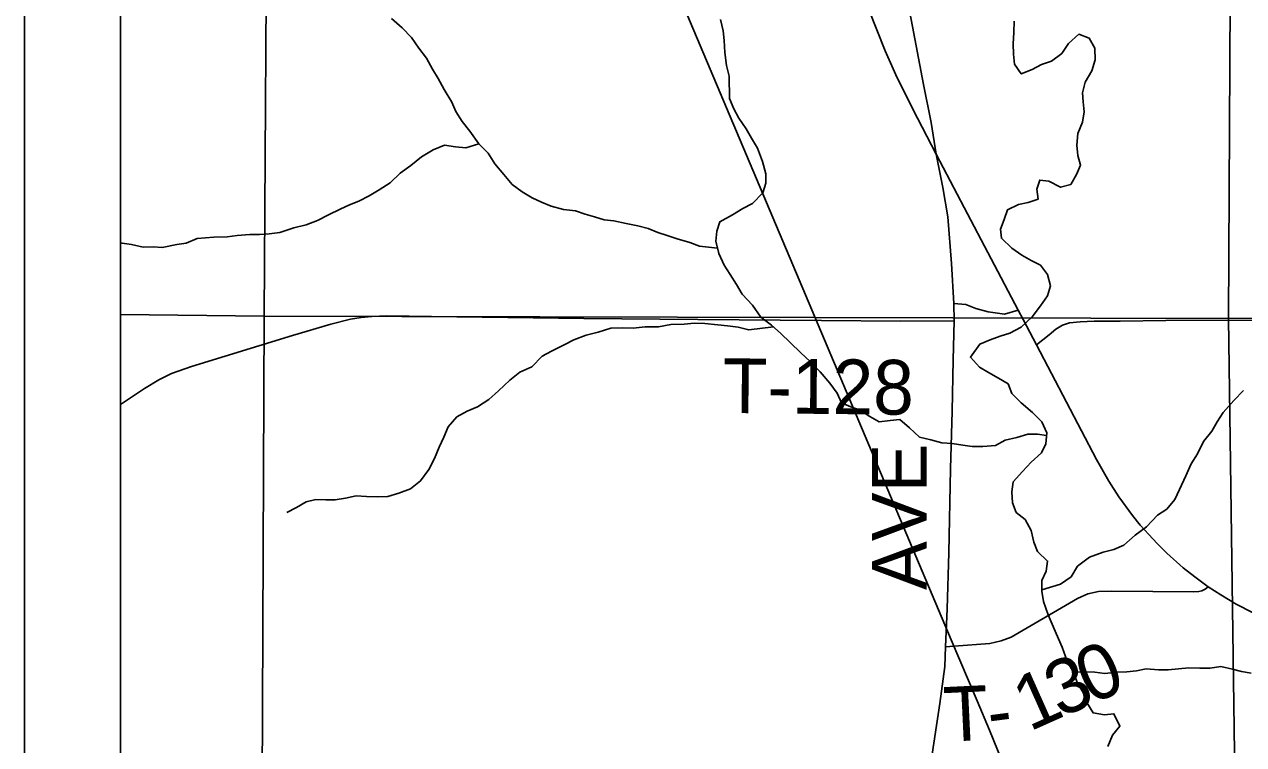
# Model space of a CAD drawing. Extents: x 0 to 34, y 0 to 22.
# Drawn here: x 2 to 3.267, y 17.55 to 18.298 of the extents above; entities that cross this region are included whole.
import ezdxf

# ---------------------------------------------------------------- set-up
doc = ezdxf.new("R2010")
doc.units = 0
for name, color, linetype in [('Default', 7, 'Continuous'), ('SH_Cut_Line', 7, 'Continuous'), ('SH_Data', 7, 'Continuous')]:
    doc.layers.add(name, color=color, linetype=linetype)

msp = doc.modelspace()

# ---------------------------------------------------------------- linework, layer by layer
at = {"layer": 'Default'}
for p, q in [((2.9665, 17.9898), (2.9659, 18.0078)), ((2.9659, 18.0078), (2.9665, 17.9898))]:
    msp.add_line(p, q, dxfattribs=at)
for points in [[(2.1, 20.9), (2.1, 17.0156)], [(2.9478, 18.1631), (2.9423, 18.1959), (2.9345, 18.2352), (2.909, 18.3706), (2.8997, 18.4145)], [(3.0159, 17.5333), (3.0031, 17.5646), (2.9901, 17.5953), (2.9633, 17.6587), (2.9067, 17.7923), (2.7985, 18.0482), (2.6541, 18.39)], [(2.8772, 18.3138), (2.8945, 18.2702), (2.9057, 18.2453), (2.9161, 18.2244), (2.9284, 18.2002), (2.9478, 18.1631)], [(2.7204, 18.0653), (2.7018, 18.0675), (2.6915, 18.0712), (2.6786, 18.0749), (2.668, 18.0785), (2.6585, 18.0815), (2.6482, 18.0859), (2.6376, 18.0885), (2.6254, 18.091), (2.6125, 18.0939), (2.6027, 18.0949), (2.5924, 18.0979), (2.5829, 18.1008), (2.5727, 18.1041), (2.5602, 18.1055), (2.5476, 18.1088), (2.5374, 18.1132), (2.5278, 18.1177), (2.5172, 18.124), (2.5069, 18.1315), (2.4984, 18.142), (2.4888, 18.153), (2.4819, 18.1639), (2.4723, 18.1736), (2.463, 18.1868), (2.455, 18.197), (2.4484, 18.2072), (2.4441, 18.217), (2.4364, 18.2302), (2.4302, 18.2415), (2.424, 18.2513), (2.4178, 18.2626), (2.4101, 18.2732), (2.4024, 18.2841), (2.3925, 18.2942), (2.3817, 18.304)], [(3.0624, 17.8709), (3.0528, 17.8723), (3.043, 17.8722), (3.0313, 17.8687), (3.0192, 17.8659), (3.0094, 17.8605), (2.9962, 17.8592), (2.9852, 17.8595), (2.9753, 17.8609), (2.9643, 17.8623), (2.9534, 17.8633), (2.942, 17.8663), (2.9302, 17.8692), (2.9199, 17.8789), (2.9099, 17.8875), (2.8997, 17.8863), (2.8884, 17.885), (2.8788, 17.8906), (2.8685, 17.897), (2.859, 17.9007), (2.8491, 17.9047), (2.8449, 17.9149), (2.8372, 17.9251), (2.8272, 17.9368), (2.8168, 17.9477), (2.8069, 17.9567), (2.7958, 17.9672), (2.7862, 17.9766), (2.7766, 17.9852), (2.7655, 17.9938), (2.7567, 18.0062), (2.746, 18.0175), (2.7401, 18.0277), (2.7336, 18.0379), (2.7274, 18.0477), (2.7216, 18.0597), (2.7188, 18.0726), (2.7198, 18.0829), (2.7227, 18.0928), (2.7359, 18.1001), (2.7468, 18.1067), (2.7569, 18.1117), (2.7674, 18.1228), (2.7707, 18.1327), (2.7705, 18.1426), (2.767, 18.1554), (2.7619, 18.1691), (2.7557, 18.1796), (2.7503, 18.1894), (2.7426, 18.2003), (2.7372, 18.2102), (2.7329, 18.2207), (2.7326, 18.2439), (2.7298, 18.2552), (2.7281, 18.2685), (2.7272, 18.281), (2.7263, 18.2912), (2.7235, 18.303)], [(3.0286, 18.3012), (3.0284, 18.2894), (3.0278, 18.2777), (3.0279, 18.2667), (3.0292, 18.2564), (3.0361, 18.2463), (3.0474, 18.2509), (3.0572, 18.256), (3.0674, 18.2595), (3.0783, 18.2676), (3.085, 18.2779), (3.0958, 18.2875), (3.1068, 18.2834), (3.1126, 18.2732), (3.1128, 18.2611), (3.1095, 18.2497), (3.1025, 18.2378), (3.0996, 18.2268), (3.1005, 18.2173), (3.1013, 18.2071), (3.0996, 18.1961), (3.0948, 18.1843), (3.0938, 18.1725), (3.0947, 18.1615), (3.0975, 18.1517), (3.0934, 18.1417), (3.0875, 18.1314), (3.0769, 18.1287), (3.0647, 18.135), (3.0553, 18.136), (3.0524, 18.1265), (3.0536, 18.1163), (3.0434, 18.1128), (3.0332, 18.1108), (3.0216, 18.1053), (3.0183, 18.0951), (3.0146, 18.0852), (3.0155, 18.0757), (3.0262, 18.0652), (3.0365, 18.0581), (3.0464, 18.0525), (3.056, 18.0476), (3.0633, 18.0379), (3.0664, 18.0261), (3.0632, 18.0159), (3.0561, 18.0055), (3.0475, 17.9941), (3.0359, 17.9833), (3.0243, 17.9771), (3.0141, 17.974), (3.0039, 17.9701), (2.993, 17.9658), (2.9833, 17.952), (2.9925, 17.9419), (3.0021, 17.9363), (3.0123, 17.9303), (3.0223, 17.9244), (3.0262, 17.9145), (3.0361, 17.9048), (3.0476, 17.8947), (3.0576, 17.8849), (3.0626, 17.8736), (3.0616, 17.8622), (3.0572, 17.8526), (3.0463, 17.843), (3.0374, 17.8335), (3.0277, 17.8227), (3.0263, 17.8121), (3.0268, 17.8007), (3.0307, 17.7909), (3.0403, 17.7834), (3.0464, 17.7721), (3.0492, 17.76), (3.0528, 17.7502), (3.0635, 17.7404), (3.0621, 17.7298), (3.0573, 17.7202), (3.0574, 17.7092), (3.0591, 17.6982), (3.0642, 17.6846), (3.0681, 17.6748), (3.0724, 17.665)], [(2.4723, 18.1736), (2.4587, 18.1697), (2.4481, 18.1707), (2.4367, 18.1725), (2.425, 18.1675), (2.4126, 18.1601), (2.4018, 18.1513), (2.3905, 18.1432), (2.38, 18.1332), (2.3688, 18.1259), (2.3582, 18.1197), (2.3477, 18.1143), (2.3379, 18.1104), (2.3281, 18.1058), (2.3161, 18.0999), (2.3048, 18.0941), (2.2928, 18.0895), (2.2799, 18.0863), (2.2656, 18.0816), (2.2543, 18.0803), (2.2444, 18.0795), (2.2342, 18.0794), (2.221, 18.0785), (2.2108, 18.0772), (2.1968, 18.0767), (2.1797, 18.0754), (2.1681, 18.0707), (2.1583, 18.0691), (2.1431, 18.0659), (2.1337, 18.0669), (2.1235, 18.0665), (2.1113, 18.069), (2.1015, 18.0704), (2.1, 18.0708)], [(2.9659, 18.0078), (2.9634, 18.0494), (2.9598, 18.0979), (2.9547, 18.1282), (2.9478, 18.1631)], [(2.9478, 18.1631), (2.9766, 18.1077), (3.0328, 18.001)], [(3.0328, 18.001), (3.0187, 17.9968), (3.0017, 17.9993), (2.9887, 18.0028), (2.9783, 18.0068), (2.9659, 18.0078)], [(2.9665, 17.9898), (2.9105, 17.9896), (2.8285, 17.9903), (2.6998, 17.9912), (2.5814, 17.9924), (2.423, 17.9942), (2.3766, 17.9949), (2.3611, 17.9944), (2.3499, 17.9932), (2.3391, 17.9915), (2.3185, 17.9863), (2.2785, 17.9747), (2.1736, 17.9424), (2.1529, 17.935), (2.1399, 17.9287), (2.125, 17.9196), (2.1, 17.9031)], [(3.0519, 17.9648), (3.038, 17.9911), (3.0328, 18.001)], [(3.0328, 18.001), (3.038, 17.9911), (3.0519, 17.9648)], [(2.7785, 17.9835), (2.7528, 17.9804), (2.7418, 17.9833), (2.7308, 17.9847), (2.7206, 17.9858), (2.7073, 17.9871), (2.696, 17.9874), (2.6858, 17.9865), (2.6718, 17.986), (2.6589, 17.9836), (2.6453, 17.9838), (2.6328, 17.9822), (2.6215, 17.9825), (2.6094, 17.9823), (2.5965, 17.978), (2.5837, 17.9749), (2.5709, 17.9702), (2.5611, 17.9648), (2.548, 17.9582), (2.5382, 17.9531), (2.5273, 17.942), (2.5149, 17.9366), (2.5044, 17.9281), (2.4928, 17.917), (2.4827, 17.9082), (2.4711, 17.9005), (2.4601, 17.8962), (2.4496, 17.89), (2.4403, 17.8797), (2.4359, 17.869), (2.4311, 17.8587), (2.4263, 17.8469), (2.4204, 17.8354), (2.4118, 17.8236), (2.4013, 17.8155), (2.3893, 17.8108), (2.3779, 17.8073), (2.3674, 17.8072), (2.3556, 17.8075), (2.345, 17.8081), (2.3337, 17.8057), (2.3231, 17.8041), (2.3133, 17.804), (2.303, 17.8043), (2.2929, 17.8019), (2.2827, 17.7961), (2.2729, 17.7907)], [(2.8565, 17.0154), (2.8631, 17.0421), (2.8838, 17.1491), (2.8944, 17.2089), (2.9064, 17.2865), (2.9142, 17.3387), (2.9228, 17.3994), (2.9334, 17.4712), (2.9418, 17.5282), (2.9514, 17.5924), (2.9565, 17.6309), (2.9575, 17.6514), (2.9591, 17.6906), (2.9608, 17.7489), (2.9624, 17.8361), (2.9641, 17.8959), (2.9654, 17.9495), (2.9665, 17.9898)], [(3.336, 17.9905), (3.1865, 17.9903), (3.1388, 17.9895), (3.112, 17.9895), (3.0973, 17.9888), (3.0863, 17.9877), (3.0788, 17.9855), (3.0721, 17.9811), (3.0652, 17.9752), (3.0519, 17.9648)], [(3.0519, 17.9648), (3.1144, 17.8459), (3.1271, 17.8232), (3.1374, 17.8069), (3.1517, 17.7878), (3.1598, 17.7778), (3.1685, 17.7679), (3.1772, 17.7586), (3.1874, 17.7487), (3.2045, 17.7334), (3.2166, 17.7239), (3.2305, 17.7136), (3.2434, 17.7054), (3.2593, 17.6957), (3.2764, 17.6868)], [(3.0574, 17.7104), (3.077, 17.7163), (3.0879, 17.724), (3.0946, 17.735), (3.107, 17.7443), (3.1213, 17.7497), (3.1322, 17.7525), (3.1428, 17.7568), (3.1544, 17.7671), (3.1664, 17.776), (3.1776, 17.7879), (3.1874, 17.7944), (3.1956, 17.8044), (3.2004, 17.8147), (3.207, 17.8288), (3.2125, 17.8413), (3.2192, 17.8517), (3.2255, 17.8646), (3.2341, 17.8753), (3.2396, 17.8849), (3.2459, 17.8948), (3.2571, 17.9071), (3.2672, 17.9174)], [(2.9575, 17.6514), (2.9665, 17.652), (3.0033, 17.6546), (3.0153, 17.6575), (3.0255, 17.6614), (3.0945, 17.7014), (3.1051, 17.7064), (3.1163, 17.7086), (3.1301, 17.7091), (3.2155, 17.7085), (3.2205, 17.7086), (3.2238, 17.7096), (3.2271, 17.7111), (3.2305, 17.7136)], [(3.0724, 17.665), (3.0786, 17.651), (3.0837, 17.6363), (3.0899, 17.6253), (3.0946, 17.6136), (3.1004, 17.6038), (3.1043, 17.5936), (3.1108, 17.5827), (3.1226, 17.5805), (3.1324, 17.5818), (3.1386, 17.5689), (3.1308, 17.5594), (3.126, 17.5479)], [(3.0899, 17.6253), (3.1126, 17.6248), (3.1228, 17.6234), (3.1353, 17.625), (3.1459, 17.6252), (3.1557, 17.6264), (3.1659, 17.6284), (3.1788, 17.6274), (3.1886, 17.6275), (3.1996, 17.6284), (3.2102, 17.6296), (3.2215, 17.629), (3.2325, 17.6291), (3.2435, 17.6307), (3.2556, 17.6282), (3.2651, 17.6256), (3.275, 17.6238)]]:
    msp.add_lwpolyline(points, dxfattribs=at)
for points in [[(2.1, 18.9883), (2.1, 17.9963), (2.2493, 17.9947), (2.2553, 18.9881)], [(2.2553, 18.9881), (3.2565, 18.9852), (3.2516, 17.9922), (2.2493, 17.9947)], [(3.2565, 18.9852), (4.2649, 18.9814), (4.2617, 17.9979), (3.2516, 17.9922)], [(2.1, 17.9963), (2.1, 17.0206), (2.2452, 17.0203), (2.2493, 17.9947)], [(2.2493, 17.9947), (3.2516, 17.9922), (3.265, 17.0154), (3.251, 17.0155), (2.2452, 17.0203)]]:
    msp.add_lwpolyline(points, close=True, dxfattribs=at)
at = {"layer": 'SH_Cut_Line'}
msp.add_lwpolyline([(2.1, 20.9), (2.1, 17.0156)], dxfattribs=at)
at = {"layer": 'SH_Data'}
for p, q in [((2, 21), (2, 14)), ((2.1, 20.9), (2.1, 14.1))]:
    msp.add_line(p, q, dxfattribs=at)

# ---------------------------------------------------------------- texts
at = {"layer": 'Default'}
for s, height, rotation, p in [('T-128', 0.05682, 359.4386, (2.7257, 17.8942)), ('AVE', 0.05682, 90, (2.9377, 17.7103)), ('0', 0.0568, 23.5034, (3.1085, 17.591)), ('3', 0.0568, 23.3797, (3.0763, 17.5771)), ('1', 0.0568, 24.0803, (3.0445, 17.5629)), ('T', 0.0568, 2.7139, (2.9566, 17.5526)), ('-', 0.0568, 7.3825, (3.004, 17.555))]:
    msp.add_text(s, height=height, rotation=rotation, dxfattribs=at).set_placement(p)

doc.saveas('drawing.dxf')
